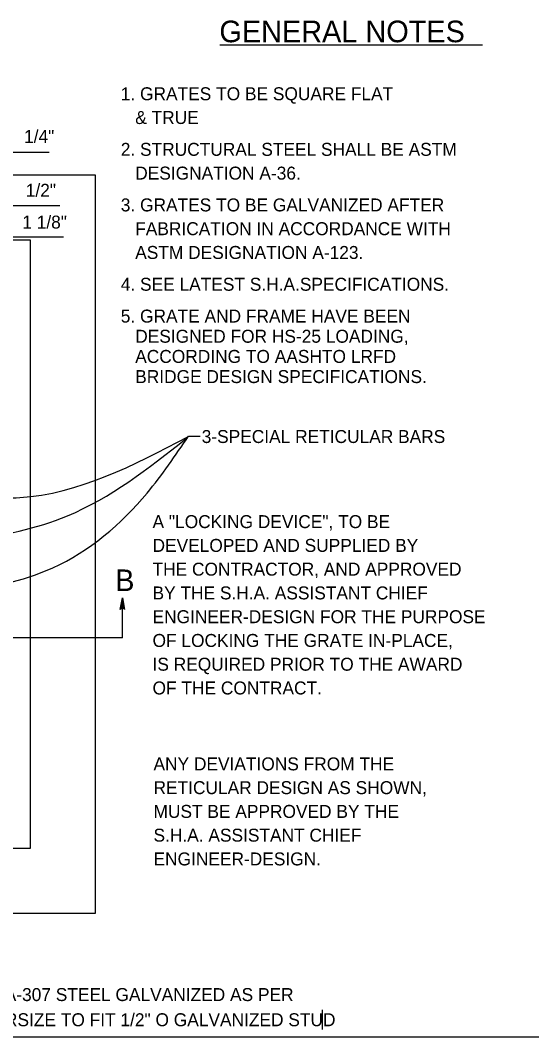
# Model space of a CAD drawing. Extents: x -0.3 to 6.9, y -6.5 to 3.5.
# Drawn here: x 4.451 to 6.852, y -1.25 to 3.455 of the extents above; entities that cross this region are included whole.
import ezdxf

# ---------------------------------------------------------------- set-up
doc = ezdxf.new("R2010")
doc.units = 0
for name, color, linetype in [('DETL-DIMS', 7, 'Continuous'), ('DETL-LINE', 7, 'Continuous'), ('DETL-NOTE', 7, 'Continuous'), ('DETL-TITL', 7, 'Continuous')]:
    doc.layers.add(name, color=color, linetype=linetype)

msp = doc.modelspace()

# ---------------------------------------------------------------- linework, layer by layer
at = {"layer": 'DETL-DIMS'}
for p, q in [((4.3851, 2.844), (4.5854, 2.844)), ((4.2816, 2.5978), (4.6336, 2.5978)), ((4.3475, 2.4529), (4.6516, 2.4529)), ((5.2304, 1.5303), (5.2837, 1.5303)), ((4.9242, 0.5969), (4.9242, 0.7823)), ((4.9242, 0.5969), (4.0133, 0.5969))]:
    msp.add_line(p, q, dxfattribs=at)
msp.add_lwpolyline([(4.9242, 0.7823), (4.9344, 0.7275), (4.9315, 0.7317), (4.9278, 0.7339), (4.9242, 0.7345), (4.9205, 0.7339), (4.9168, 0.7317), (4.9139, 0.7275), (4.9242, 0.7823), (4.9168, 0.7317), (4.9205, 0.7339), (4.9242, 0.7823), (4.9242, 0.7345), (4.9278, 0.7339), (4.9242, 0.7823), (4.9315, 0.7317)], dxfattribs=at)
for points in [[(4.1468, 0.8027), (4.6025, 0.9206), (5.038, 1.2663), (5.2304, 1.5303)], [(4.1749, 1.2548), (4.4489, 1.2459), (5.2267, 1.5265)], [(4.2146, 1.041), (4.669, 1.1613), (5.2191, 1.5189)]]:
    msp.add_spline(points, degree=3, dxfattribs=at)
at = {"layer": 'DETL-LINE'}
for p, q in [((4.7992, 2.7381), (1.0722, 2.7381)), ((4.7992, -0.6784), (4.7992, 2.7381)), ((4.4981, 2.4369), (1.3734, 2.4369)), ((4.4981, -0.3772), (4.4981, 2.4369)), ((1.3734, -0.3772), (4.4981, -0.3772)), ((1.0722, -0.6784), (4.7992, -0.6784))]:
    msp.add_line(p, q, dxfattribs=at)
at = {"layer": 'DETL-NOTE'}
for p, q in [((5.3748, 3.341), (6.5925, 3.341)), ((5.8493, -1.1254), (5.8493, -1.2173)), ((3.2016, -1.2498), (6.8521, -1.2498))]:
    msp.add_line(p, q, dxfattribs=at)

# ---------------------------------------------------------------- texts
for s, height, p in [('GENERAL NOTES', 0.1, (5.3733, 3.3536)), ('1. GRATES TO BE SQUARE FLAT ', 0.06, (4.9165, 3.0851)), ('   & TRUE', 0.06, (4.9165, 2.9751)), ('1/4"', 0.06, (4.4686, 2.8876)), ('2. STRUCTURAL STEEL SHALL BE ASTM', 0.06, (4.9165, 2.8278)), ('   DESIGNATION A-36.', 0.06, (4.9165, 2.7178)), ('1/2"', 0.06, (4.4765, 2.6382)), ('3. GRATES TO BE GALVANIZED AFTER ', 0.06, (4.9165, 2.5705)), ('1 1/8"', 0.06, (4.4603, 2.491)), ('   FABRICATION IN ACCORDANCE WITH', 0.06, (4.9165, 2.4605)), ('   ASTM DESIGNATION A-123.', 0.06, (4.9165, 2.3505)), ('4. SEE LATEST S.H.A.SPECIFICATIONS.', 0.06, (4.9165, 2.2032)), ('5. GRATE AND FRAME HAVE BEEN ', 0.06, (4.9165, 2.0559)), ('   DESIGNED FOR HS-25 LOADING,', 0.06, (4.9165, 1.9626)), ('   ACCORDING TO AASHTO LRFD ', 0.06, (4.9165, 1.8692)), ('   BRIDGE DESIGN SPECIFICATIONS.', 0.06, (4.9165, 1.7759)), ('3-SPECIAL RETICULAR BARS', 0.06, (5.2913, 1.4984)), ('A "LOCKING DEVICE", TO BE ', 0.06, (5.0636, 1.1044)), ('DEVELOPED AND SUPPLIED BY ', 0.06, (5.0636, 0.9944)), ('THE CONTRACTOR, AND APPROVED ', 0.06, (5.0636, 0.8844)), ('BY THE S.H.A. ASSISTANT CHIEF ', 0.06, (5.0636, 0.7744)), ('ENGINEER-DESIGN FOR THE PURPOSE', 0.06, (5.0636, 0.6644)), ('OF LOCKING THE GRATE IN-PLACE, ', 0.06, (5.0636, 0.5544)), ('IS REQUIRED PRIOR TO THE AWARD ', 0.06, (5.0636, 0.4444)), ('OF THE CONTRACT.', 0.06, (5.0636, 0.3344)), ('ANY DEVIATIONS FROM THE', 0.06, (5.0681, -0.017)), ('RETICULAR DESIGN AS SHOWN,', 0.06, (5.0681, -0.127)), ('MUST BE APPROVED BY THE', 0.06, (5.0681, -0.237)), ('S.H.A. ASSISTANT CHIEF ', 0.06, (5.0681, -0.347)), ('ENGINEER-DESIGN.  ', 0.06, (5.0681, -0.457)), (' -13 HEX THIN NUTS TYPE A-307 STEEL GALVANIZED AS PER', 0.06, (3.3492, -1.0849)), ('A.S.T.M. A-153 & TAPPED OVERSIZE TO FIT 1/2" O GALVANIZED STUD', 0.06, (3.2208, -1.2014))]:
    msp.add_text(s, height=height, dxfattribs=at).set_placement(p)
at = {"layer": 'DETL-TITL'}
msp.add_text('B', height=0.1, dxfattribs=at).set_placement((4.8906, 0.813))

doc.saveas('drawing.dxf')
